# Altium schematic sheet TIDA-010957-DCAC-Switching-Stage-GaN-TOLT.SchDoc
size 558 x 431 mm; Date: Not shown in title block; ApprovedBy: Not shown in title block; CheckedBy: Not shown in title block; Author: Not shown in title block; CompanyName: Not shown in title block; Engineer: Not shown in title block; Organization: Not shown in title block; Address1: Not shown in title block; Address2: Not shown in title block; Address3: Not shown in title block; Address4: Not shown in title block; DocumentNumber: 1; Revision: Use project parameter SCH_Rev; SheetNumber: 12; SheetTotal: 12; PageSetup: Record=PageOptions¦CenterHorizontal=True¦CenterVertical=True¦PrintScale=1.00¦XCorrection=1.00¦YCorrection=1.00¦PrintKind=0¦BorderSize=5000000¦LeftOffset=0¦BottomOffset=0¦Orientation=2¦PaperLength=1000¦PaperWidth=1000¦Scale=100¦PaperSource=15¦PrintQuality=600¦MediaType=1¦DitherType=10¦PaperKind=Letter¦PrintScaleMode=1
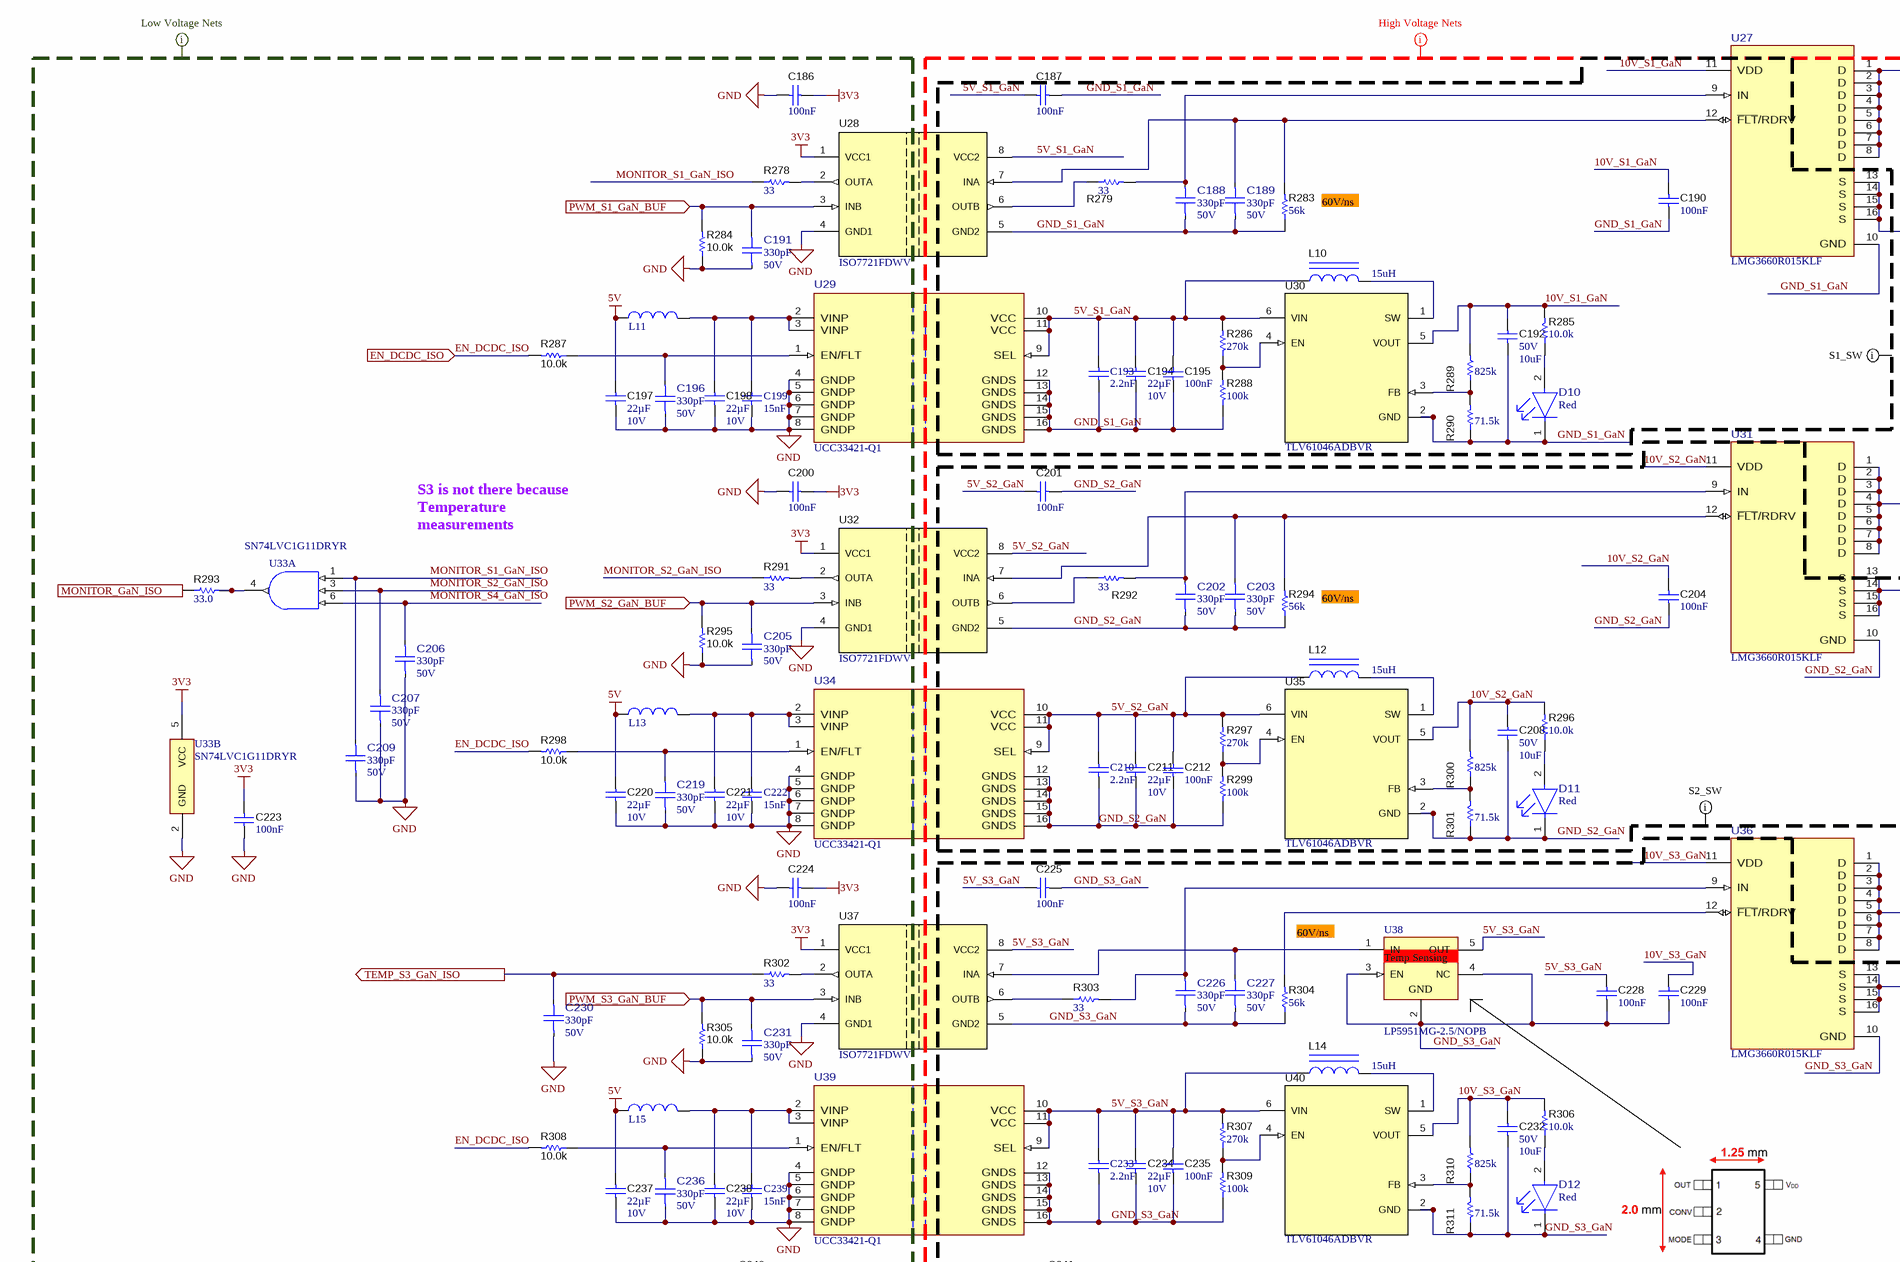
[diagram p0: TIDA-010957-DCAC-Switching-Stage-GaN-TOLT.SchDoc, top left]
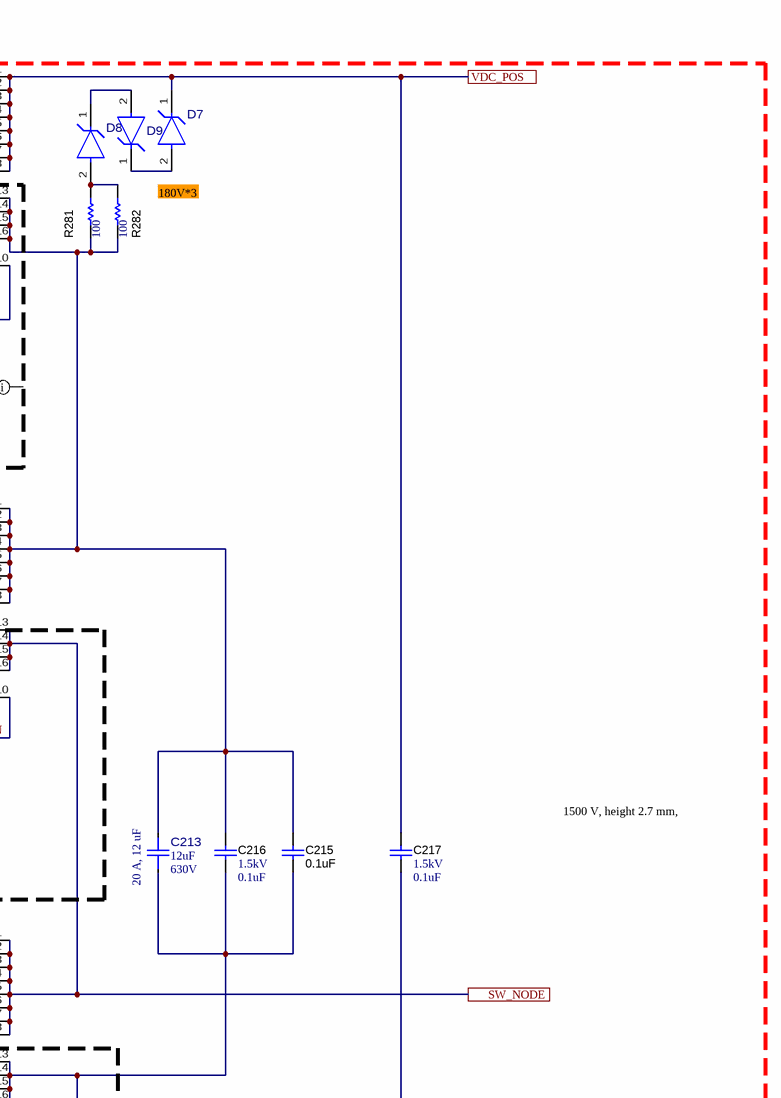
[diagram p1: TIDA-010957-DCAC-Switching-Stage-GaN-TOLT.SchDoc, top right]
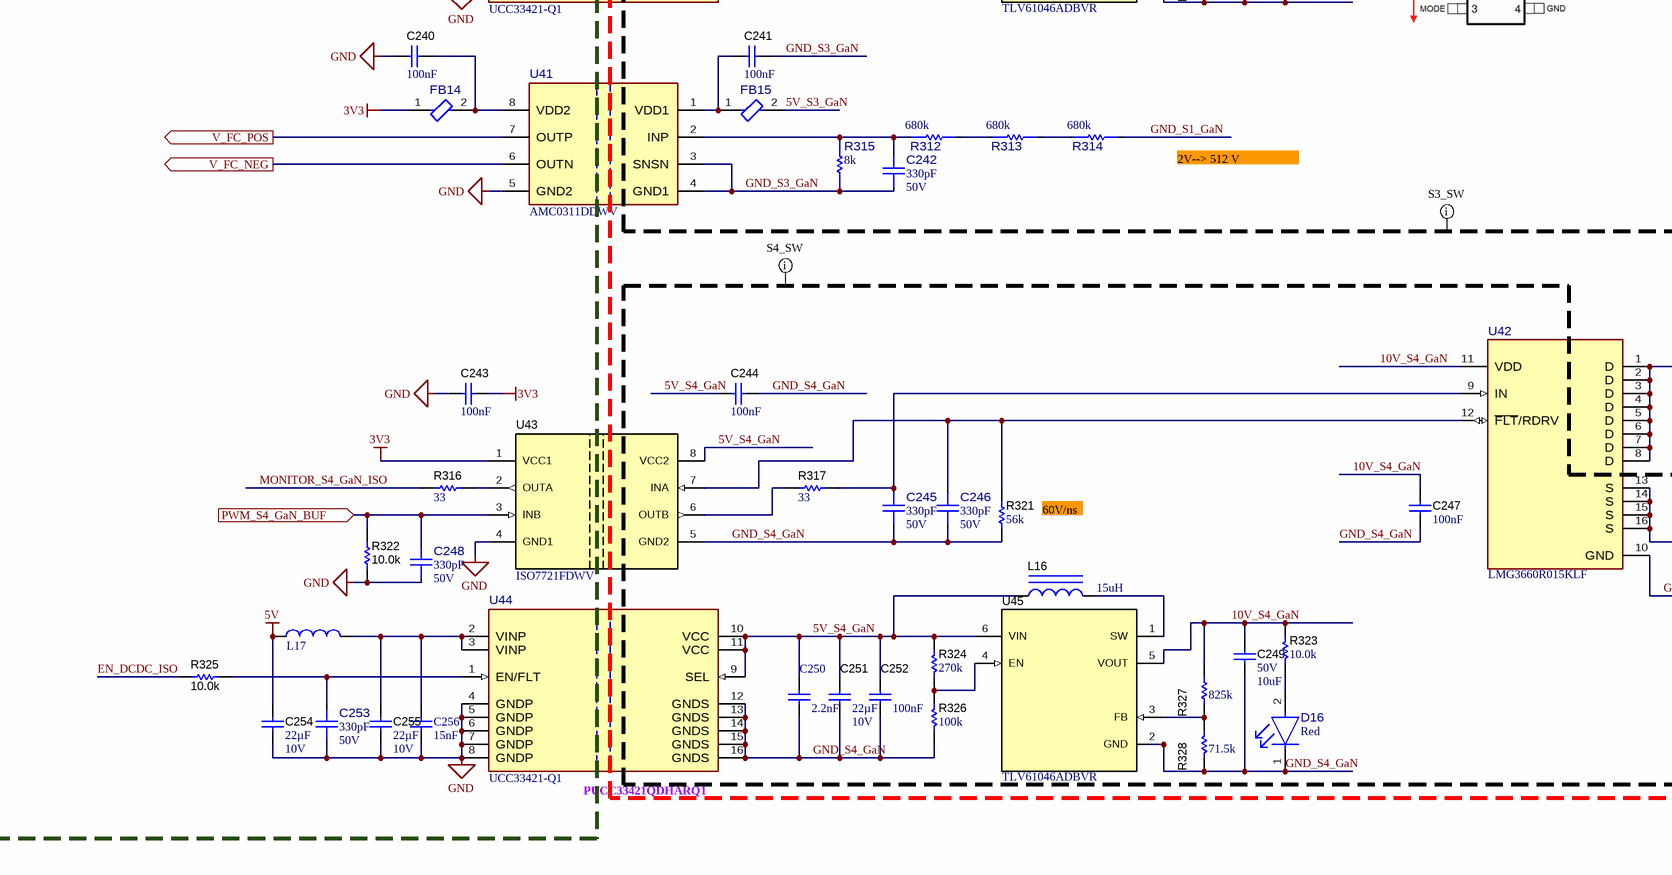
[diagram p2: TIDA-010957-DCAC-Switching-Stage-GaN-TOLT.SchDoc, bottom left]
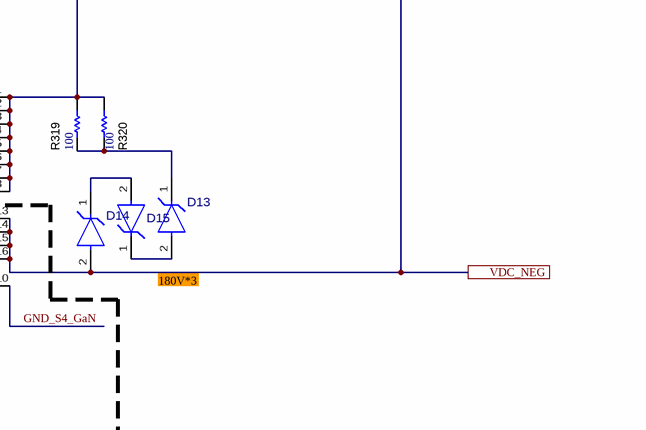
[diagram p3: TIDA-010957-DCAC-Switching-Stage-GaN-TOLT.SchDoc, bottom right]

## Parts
C186  Cap_F: 100nF  [0603]  (hidden comment: 06033C104JAT2A)
C187  Cap_F: 100nF  [0603]  (hidden comment: 06033C104JAT2A)
C188  ValueDisplayed: 330pF  VDC_V: 50V  [FP-CGA3E2C0G1H331J080AA_0603-MFG]  (hidden comment: CGA3E2C0G1H331J080AA)
C189  ValueDisplayed: 330pF  VDC_V: 50V  [FP-CGA3E2C0G1H331J080AA_0603-MFG]  (hidden comment: CGA3E2C0G1H331J080AA)
C190  Cap_F: 100nF  [0603]  (hidden comment: 06033C104JAT2A)
C191  ValueDisplayed: 330pF  VDC_V: 50V  [FP-CGA3E2C0G1H331J080AA_0603-MFG]  (hidden comment: CGA3E2C0G1H331J080AA)
C192  VDC_V: 50V  ValueDisplayed: 10uF  [1206_180]  (hidden comment: GRT31CR61H106KE01L)
C193  Cap_F: 2.2nF  [WCAP-CSGP_0402_L1W0.5H0.5]  (hidden comment: 885012205063)
C194  Cap_F: 22µF  VDC_V: 10V  [0805_HV]  (hidden comment: GRM21BZ71A226ME15L)
C195  Cap_F: 100nF  [0603]  (hidden comment: 06033C104JAT2A)
C196  ValueDisplayed: 330pF  VDC_V: 50V  [FP-CGA3E2C0G1H331J080AA_0603-MFG]  (hidden comment: CGA3E2C0G1H331J080AA)
C197  Cap_F: 22µF  VDC_V: 10V  [0805_HV]  (hidden comment: GRM21BZ71A226ME15L)
C198  Cap_F: 22µF  VDC_V: 10V  [0805_HV]  (hidden comment: GRM21BZ71A226ME15L)
C199  Cap_F: 15nF  [WCAP-CSGP_0402_L1W0.5H0.5]  (hidden comment: 885012205051)
C200  Cap_F: 100nF  [0603]  (hidden comment: 06033C104JAT2A)
C201  Cap_F: 100nF  [0603]  (hidden comment: 06033C104JAT2A)
C202  ValueDisplayed: 330pF  VDC_V: 50V  [FP-CGA3E2C0G1H331J080AA_0603-MFG]  (hidden comment: CGA3E2C0G1H331J080AA)
C203  ValueDisplayed: 330pF  VDC_V: 50V  [FP-CGA3E2C0G1H331J080AA_0603-MFG]  (hidden comment: CGA3E2C0G1H331J080AA)
C204  Cap_F: 100nF  [0603]  (hidden comment: 06033C104JAT2A)
C205  ValueDisplayed: 330pF  VDC_V: 50V  [FP-CGA3E2C0G1H331J080AA_0603-MFG]  (hidden comment: CGA3E2C0G1H331J080AA)
C206  ValueDisplayed: 330pF  VDC_V: 50V  [FP-CGA3E2C0G1H331J080AA_0603-MFG]  (hidden comment: CGA3E2C0G1H331J080AA)
C207  ValueDisplayed: 330pF  VDC_V: 50V  [FP-CGA3E2C0G1H331J080AA_0603-MFG]  (hidden comment: CGA3E2C0G1H331J080AA)
C208  VDC_V: 50V  ValueDisplayed: 10uF  [1206_180]  (hidden comment: GRT31CR61H106KE01L)
C209  ValueDisplayed: 330pF  VDC_V: 50V  [FP-CGA3E2C0G1H331J080AA_0603-MFG]  (hidden comment: CGA3E2C0G1H331J080AA)
C210  Cap_F: 2.2nF  [WCAP-CSGP_0402_L1W0.5H0.5]  (hidden comment: 885012205063)
C211  Cap_F: 22µF  VDC_V: 10V  [0805_HV]  (hidden comment: GRM21BZ71A226ME15L)
C212  Cap_F: 100nF  [0603]  (hidden comment: 06033C104JAT2A)
C213  ValueDisplayed: 12uF  VDC_V: 630V  [FP-B32676G6126K000_RADIAL-MFG]  (hidden comment: B32676G6126K000)
C215  ValueDisplayed: 0.1uF  [1812_254]  (hidden comment: C1812W104KDRACTU)
C216  VDC_V: 1.5kV  ValueDisplayed: 0.1uF  [2225]  (hidden comment: C2225C104KFRACTU)
C217  VDC_V: 1.5kV  ValueDisplayed: 0.1uF  [2225]  (hidden comment: C2225C104KFRACTU)
C219  ValueDisplayed: 330pF  VDC_V: 50V  [FP-CGA3E2C0G1H331J080AA_0603-MFG]  (hidden comment: CGA3E2C0G1H331J080AA)
C220  Cap_F: 22µF  VDC_V: 10V  [0805_HV]  (hidden comment: GRM21BZ71A226ME15L)
C221  Cap_F: 22µF  VDC_V: 10V  [0805_HV]  (hidden comment: GRM21BZ71A226ME15L)
C222  Cap_F: 15nF  [WCAP-CSGP_0402_L1W0.5H0.5]  (hidden comment: 885012205051)
C223  Cap_F: 100nF  [0603]  (hidden comment: 06033C104JAT2A)
C224  Cap_F: 100nF  [0603]  (hidden comment: 06033C104JAT2A)
C225  Cap_F: 100nF  [0603]  (hidden comment: 06033C104JAT2A)
C226  ValueDisplayed: 330pF  VDC_V: 50V  [FP-CGA3E2C0G1H331J080AA_0603-MFG]  (hidden comment: CGA3E2C0G1H331J080AA)
C227  ValueDisplayed: 330pF  VDC_V: 50V  [FP-CGA3E2C0G1H331J080AA_0603-MFG]  (hidden comment: CGA3E2C0G1H331J080AA)
C228  Cap_F: 100nF  [0603]  (hidden comment: 06033C104JAT2A)
C229  Cap_F: 100nF  [0603]  (hidden comment: 06033C104JAT2A)
C230  ValueDisplayed: 330pF  VDC_V: 50V  [FP-CGA3E2C0G1H331J080AA_0603-MFG]  (hidden comment: CGA3E2C0G1H331J080AA)
C231  ValueDisplayed: 330pF  VDC_V: 50V  [FP-CGA3E2C0G1H331J080AA_0603-MFG]  (hidden comment: CGA3E2C0G1H331J080AA)
C232  VDC_V: 50V  ValueDisplayed: 10uF  [1206_180]  (hidden comment: GRT31CR61H106KE01L)
C233  Cap_F: 2.2nF  [WCAP-CSGP_0402_L1W0.5H0.5]  (hidden comment: 885012205063)
C234  Cap_F: 22µF  VDC_V: 10V  [0805_HV]  (hidden comment: GRM21BZ71A226ME15L)
C235  Cap_F: 100nF  [0603]  (hidden comment: 06033C104JAT2A)
C236  ValueDisplayed: 330pF  VDC_V: 50V  [FP-CGA3E2C0G1H331J080AA_0603-MFG]  (hidden comment: CGA3E2C0G1H331J080AA)
C237  Cap_F: 22µF  VDC_V: 10V  [0805_HV]  (hidden comment: GRM21BZ71A226ME15L)
C238  Cap_F: 22µF  VDC_V: 10V  [0805_HV]  (hidden comment: GRM21BZ71A226ME15L)
C239  Cap_F: 15nF  [WCAP-CSGP_0402_L1W0.5H0.5]  (hidden comment: 885012205051)
C240  Cap_F: 100nF  [0603]  (hidden comment: 06033C104JAT2A)
C241  Cap_F: 100nF  [0603]  (hidden comment: 06033C104JAT2A)
C242  ValueDisplayed: 330pF  VDC_V: 50V  [FP-CGA3E2C0G1H331J080AA_0603-MFG]  (hidden comment: CGA3E2C0G1H331J080AA)
C243  Cap_F: 100nF  [0603]  (hidden comment: 06033C104JAT2A)
C244  Cap_F: 100nF  [0603]  (hidden comment: 06033C104JAT2A)
C245  ValueDisplayed: 330pF  VDC_V: 50V  [FP-CGA3E2C0G1H331J080AA_0603-MFG]  (hidden comment: CGA3E2C0G1H331J080AA)
C246  ValueDisplayed: 330pF  VDC_V: 50V  [FP-CGA3E2C0G1H331J080AA_0603-MFG]  (hidden comment: CGA3E2C0G1H331J080AA)
C247  Cap_F: 100nF  [0603]  (hidden comment: 06033C104JAT2A)
C248  ValueDisplayed: 330pF  VDC_V: 50V  [FP-CGA3E2C0G1H331J080AA_0603-MFG]  (hidden comment: CGA3E2C0G1H331J080AA)
C249  VDC_V: 50V  ValueDisplayed: 10uF  [1206_180]  (hidden comment: GRT31CR61H106KE01L)
C250  Cap_F: 2.2nF  [WCAP-CSGP_0402_L1W0.5H0.5]  (hidden comment: 885012205063)
C251  Cap_F: 22µF  VDC_V: 10V  [0805_HV]  (hidden comment: GRM21BZ71A226ME15L)
C252  Cap_F: 100nF  [0603]  (hidden comment: 06033C104JAT2A)
C253  ValueDisplayed: 330pF  VDC_V: 50V  [FP-CGA3E2C0G1H331J080AA_0603-MFG]  (hidden comment: CGA3E2C0G1H331J080AA)
C254  Cap_F: 22µF  VDC_V: 10V  [0805_HV]  (hidden comment: GRM21BZ71A226ME15L)
C255  Cap_F: 22µF  VDC_V: 10V  [0805_HV]  (hidden comment: GRM21BZ71A226ME15L)
C256  Cap_F: 15nF  [WCAP-CSGP_0402_L1W0.5H0.5]  (hidden comment: 885012205051)
D7  ZGL41-180A-E3/96  [FP-ZGL41-180A-E3/96_GL41-MFG]  (value not drawn)
D8  ZGL41-180A-E3/96  [FP-ZGL41-180A-E3/96_GL41-MFG]  (value not drawn)
D9  ZGL41-180A-E3/96  [FP-ZGL41-180A-E3/96_GL41-MFG]  (value not drawn)
D10  Color: Red  [FP-APG1608SURKC_T_0603-MFG]  (hidden comment: APG1608SURKC/T)
D11  Color: Red  [FP-APG1608SURKC_T_0603-MFG]  (hidden comment: APG1608SURKC/T)
D12  Color: Red  [FP-APG1608SURKC_T_0603-MFG]  (hidden comment: APG1608SURKC/T)
D13  ZGL41-180A-E3/96  [FP-ZGL41-180A-E3/96_GL41-MFG]  (value not drawn)
D14  ZGL41-180A-E3/96  [FP-ZGL41-180A-E3/96_GL41-MFG]  (value not drawn)
D15  ZGL41-180A-E3/96  [FP-ZGL41-180A-E3/96_GL41-MFG]  (value not drawn)
D16  Color: Red  [FP-APG1608SURKC_T_0603-MFG]  (hidden comment: APG1608SURKC/T)
FB14  MH1608-601Y  [FP-MH1608-601Y_0603-MFG]  (value not drawn)
FB15  MH1608-601Y  [FP-MH1608-601Y_0603-MFG]  (value not drawn)
L10  ValueDisplayed: 15uH  [SDR0302]  (hidden comment: SDR0302-150ML)
L11  74479763222  [WE-PMI_0603_L1.6W0.8H0.8]  (value not drawn)
L12  ValueDisplayed: 15uH  [SDR0302]  (hidden comment: SDR0302-150ML)
L13  74479763222  [WE-PMI_0603_L1.6W0.8H0.8]  (value not drawn)
L14  ValueDisplayed: 15uH  [SDR0302]  (hidden comment: SDR0302-150ML)
L15  74479763222  [WE-PMI_0603_L1.6W0.8H0.8]  (value not drawn)
L16  ValueDisplayed: 15uH  [SDR0302]  (hidden comment: SDR0302-150ML)
L17  74479763222  [WE-PMI_0603_L1.6W0.8H0.8]  (value not drawn)
R278  ValueDisplayed: 33  [0603]  (hidden comment: CRCW060333R0JNEA)
R279  ValueDisplayed: 33  [0603]  (hidden comment: CRCW060333R0JNEA)
R281  ValueDisplayed: 100  [1206]  (hidden comment: CRCW1206100RFKEAHP)
R282  ValueDisplayed: 100  [1206]  (hidden comment: CRCW1206100RFKEAHP)
R283  ValueDisplayed: 56k  [0603]  (hidden comment: CRCW060356K0JNEA)
R284  ValueDisplayed: 10.0k  [0603]  (hidden comment: CRCW060310K0FKEA)
R285  ValueDisplayed: 10.0k  [0603]  (hidden comment: RC0603FR-0710KL)
R286  ValueDisplayed: 270k  [0603]  (hidden comment: RC0603FR-07270KL)
R287  ValueDisplayed: 10.0k  [0603]  (hidden comment: CRCW060310K0FKEA)
R288  ValueDisplayed: 100k  [0603]  (hidden comment: RC0603FR-07100KL)
R289  ValueDisplayed: 825k  [0603]  (hidden comment: RC0603FR-07825KL)
R290  ValueDisplayed: 71.5k  [0603]  (hidden comment: RC0603FR-0771K5L)
R291  ValueDisplayed: 33  [0603]  (hidden comment: CRCW060333R0JNEA)
R292  ValueDisplayed: 33  [0603]  (hidden comment: CRCW060333R0JNEA)
R293  ValueDisplayed: 33.0  [0402L]  (hidden comment: ERJ-2RKF33R0X)
R294  ValueDisplayed: 56k  [0603]  (hidden comment: CRCW060356K0JNEA)
R295  ValueDisplayed: 10.0k  [0603]  (hidden comment: CRCW060310K0FKEA)
R296  ValueDisplayed: 10.0k  [0603]  (hidden comment: RC0603FR-0710KL)
R297  ValueDisplayed: 270k  [0603]  (hidden comment: RC0603FR-07270KL)
R298  ValueDisplayed: 10.0k  [0603]  (hidden comment: CRCW060310K0FKEA)
R299  ValueDisplayed: 100k  [0603]  (hidden comment: RC0603FR-07100KL)
R300  ValueDisplayed: 825k  [0603]  (hidden comment: RC0603FR-07825KL)
R301  ValueDisplayed: 71.5k  [0603]  (hidden comment: RC0603FR-0771K5L)
R302  ValueDisplayed: 33  [0603]  (hidden comment: CRCW060333R0JNEA)
R303  ValueDisplayed: 33  [0603]  (hidden comment: CRCW060333R0JNEA)
R304  ValueDisplayed: 56k  [0603]  (hidden comment: CRCW060356K0JNEA)
R305  ValueDisplayed: 10.0k  [0603]  (hidden comment: CRCW060310K0FKEA)
R306  ValueDisplayed: 10.0k  [0603]  (hidden comment: RC0603FR-0710KL)
R307  ValueDisplayed: 270k  [0603]  (hidden comment: RC0603FR-07270KL)
R308  ValueDisplayed: 10.0k  [0603]  (hidden comment: CRCW060310K0FKEA)
R309  ValueDisplayed: 100k  [0603]  (hidden comment: RC0603FR-07100KL)
R310  ValueDisplayed: 825k  [0603]  (hidden comment: RC0603FR-07825KL)
R311  ValueDisplayed: 71.5k  [0603]  (hidden comment: RC0603FR-0771K5L)
R312  value 680k  [FP-TNPV0805680KBEEA_0805-MFG]  (hidden comment: TNPV0805680KBEEA)
R313  value 680k  [FP-TNPV0805680KBEEA_0805-MFG]  (hidden comment: TNPV0805680KBEEA)
R314  value 680k  [FP-TNPV0805680KBEEA_0805-MFG]  (hidden comment: TNPV0805680KBEEA)
R315  value 8k  [FP-RT0603BRE078KL_0603-MFG]  (hidden comment: RT0603BRE078KL)
R316  ValueDisplayed: 33  [0603]  (hidden comment: CRCW060333R0JNEA)
R317  ValueDisplayed: 33  [0603]  (hidden comment: CRCW060333R0JNEA)
R319  ValueDisplayed: 100  [1206]  (hidden comment: CRCW1206100RFKEAHP)
R320  ValueDisplayed: 100  [1206]  (hidden comment: CRCW1206100RFKEAHP)
R321  ValueDisplayed: 56k  [0603]  (hidden comment: CRCW060356K0JNEA)
R322  ValueDisplayed: 10.0k  [0603]  (hidden comment: CRCW060310K0FKEA)
R323  ValueDisplayed: 10.0k  [0603]  (hidden comment: RC0603FR-0710KL)
R324  ValueDisplayed: 270k  [0603]  (hidden comment: RC0603FR-07270KL)
R325  ValueDisplayed: 10.0k  [0603]  (hidden comment: CRCW060310K0FKEA)
R326  ValueDisplayed: 100k  [0603]  (hidden comment: RC0603FR-07100KL)
R327  ValueDisplayed: 825k  [0603]  (hidden comment: RC0603FR-07825KL)
R328  ValueDisplayed: 71.5k  [0603]  (hidden comment: RC0603FR-0771K5L)
U27  LMG3660R015KLF  [KLF0016A-MFG]
U28  ISO7721FDWV  [DWV0008A]
U29  UCC33421-Q1  [DWX0016A-MFG]
U30  TLV61046ADBVR  [DBV0006A_N]
U31  LMG3660R015KLF  [KLF0016A-MFG]
U32  ISO7721FDWV  [DWV0008A]
U33  SN74LVC1G11DRYR  [DRY0006A]  (parts A,B of 2)
U34  UCC33421-Q1  [DWX0016A-MFG]
U35  TLV61046ADBVR  [DBV0006A_N]
U36  LMG3660R015KLF  [KLF0016A-MFG]
U37  ISO7721FDWV  [DWV0008A]
U38  LP5951MG-2.5/NOPB  [DCK0005A_N]
U39  UCC33421-Q1  [DWX0016A-MFG]
U40  TLV61046ADBVR  [DBV0006A_N]
U41  AMC0311DDWV  [DWV0008A-MFG]
U42  LMG3660R015KLF  [KLF0016A-MFG]
U43  ISO7721FDWV  [DWV0008A]
U44  UCC33421-Q1  [DWX0016A-MFG]
U45  TLV61046ADBVR  [DBV0006A_N]

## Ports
EN_DCDC_ISO (in), MONITOR_GaN_ISO (out), PWM_S1_GaN_BUF (in), PWM_S2_GaN_BUF (in), PWM_S3_GaN_BUF (in), PWM_S4_GaN_BUF (in), SW_NODE, TEMP_S3_GaN_ISO (out), V_FC_NEG (out), V_FC_POS (out), VDC_NEG, VDC_POS

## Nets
3V3: C186.1 C200.1 C223.1 C224.1 C243.1 FB14.1 U28.1(VCC1) U32.1(VCC1) U33.5(VCC) U37.1(VCC1) U43.1(VCC1)
5V: C197.1 C220.1 C237.1 C254.1 L11.2 L13.2 L15.2 L17.2
GND: C186.2 C191.1 C196.1 C197.2 C198.2 C199.1 C200.2 C205.1 C206.1 C207.1 C209.1 C219.1 C220.2 C221.2 C222.1 C223.2 C224.2 C230.1 C231.1 C236.1 C237.2 C238.2 C239.1 C240.2 C243.2 C248.1 C253.1 C254.2 C255.2 C256.1 R284.1 R295.1 R305.1 R322.1 U28.4(GND1) U29.4(GNDP) U29.5(GNDP) U29.6(GNDP) U29.7(GNDP) U29.8(GNDP) U32.4(GND1) U33.2(GND) U34.4(GNDP) U34.5(GNDP) U34.6(GNDP) U34.7(GNDP) U34.8(GNDP) U37.4(GND1) U39.4(GNDP) U39.5(GNDP) U39.6(GNDP) U39.7(GNDP) U39.8(GNDP) U41.5(GND2) U43.4(GND1) U44.4(GNDP) U44.5(GNDP) U44.6(GNDP) U44.7(GNDP) U44.8(GNDP)
5V_S1_GaN: C187.1 C193.2 C194.1 C195.1 L10.2 R286.2 U28.8(VCC2) U29.9(SEL) U29.10(VCC) U29.11(VCC) U30.6(VIN)
5V_S2_GaN: C201.1 C210.2 C211.1 C212.1 L12.2 R297.2 U32.8(VCC2) U34.9(SEL) U34.10(VCC) U34.11(VCC) U35.6(VIN)
5V_S3_GaN: C225.1 C228.1 C233.2 C234.1 C235.1 FB15.2 L14.2 R307.2 U37.8(VCC2) U38.5(OUT) U39.9(SEL) U39.10(VCC) U39.11(VCC) U40.6(VIN)
5V_S4_GaN: C244.1 C250.2 C251.1 C252.1 L16.2 R324.2 U43.8(VCC2) U44.9(SEL) U44.10(VCC) U44.11(VCC) U45.6(VIN)
10V_S1_GaN: C190.1 C192.1 R285.2 R289.2 U27.11(VDD) U30.5(VOUT)
10V_S2_GaN: C204.1 C208.1 R296.2 R300.2 U31.11(VDD) U35.5(VOUT)
10V_S3_GaN: C229.1 C232.1 R306.2 R310.2 U36.11(VDD) U40.5(VOUT)
10V_S4_GaN: C247.1 C249.1 R323.2 R327.2 U42.11(VDD) U45.5(VOUT)
EN_DCDC_ISO: R287.2 R298.2 R308.2 R325.2 ; port EN_DCDC_ISO
GND_S1_GaN: C187.2 C188.1 C189.1 C190.2 C192.2 C193.1 C194.2 C195.2 D10.1(CATHODE) R283.1 R288.1 R290.1 R314.2 U27.10(GND) U28.5(GND2) U29.12(GNDS) U29.13(GNDS) U29.14(GNDS) U29.15(GNDS) U29.16(GNDS) U30.2(GND)
GND_S2_GaN: C201.2 C202.1 C203.1 C204.2 C208.2 C210.1 C211.2 C212.2 D11.1(CATHODE) R294.1 R299.1 R301.1 U31.10(GND) U32.5(GND2) U34.12(GNDS) U34.13(GNDS) U34.14(GNDS) U34.15(GNDS) U34.16(GNDS) U35.2(GND)
GND_S3_GaN: C225.2 C226.1 C227.1 C228.2 C229.2 C232.2 C233.1 C234.2 C235.2 C241.2 C242.1 D12.1(CATHODE) R304.1 R309.1 R311.1 R315.1 U36.10(GND) U37.5(GND2) U38.2(GND) U38.3(EN) U38.4(NC) U39.12(GNDS) U39.13(GNDS) U39.14(GNDS) U39.15(GNDS) U39.16(GNDS) U40.2(GND) U41.3(SNSN) U41.4(GND1)
GND_S4_GaN: C244.2 C245.1 C246.1 C247.2 C249.2 C250.1 C251.2 C252.2 D16.1(CATHODE) R321.1 R326.1 R328.1 U42.10(GND) U43.5(GND2) U44.12(GNDS) U44.13(GNDS) U44.14(GNDS) U44.15(GNDS) U44.16(GNDS) U45.2(GND)
MONITOR_GaN_ISO: R293.1 ; port MONITOR_GaN_ISO
MONITOR_S1_GaN_ISO: C209.2 R278.1 U33.1(A)
MONITOR_S2_GaN_ISO: C207.2 R291.1 U33.3(B)
MONITOR_S4_GaN_ISO: C206.2 R316.1 U33.6(C)
PWM_S1_GaN_BUF: C191.2 R284.2 U28.3(INB) ; port PWM_S1_GaN_BUF
PWM_S2_GaN_BUF: C205.2 R295.2 U32.3(INB) ; port PWM_S2_GaN_BUF
PWM_S3_GaN_BUF: C231.2 R305.2 U37.3(INB) ; port PWM_S3_GaN_BUF
PWM_S4_GaN_BUF: C248.2 R322.2 U43.3(INB) ; port PWM_S4_GaN_BUF
SW_NODE: U31.13(S) U31.14(S) U31.15(S) U31.16(S) U36.1(D) U36.2(D) U36.3(D) U36.4(D) U36.5(D) U36.6(D) U36.7(D) U36.8(D) ; port SW_NODE
TEMP_S3_GaN_ISO: C230.2 R302.1 ; port TEMP_S3_GaN_ISO
V_FC_NEG: U41.6(OUTN) ; port V_FC_NEG
V_FC_POS: U41.7(OUTP) ; port V_FC_POS
VDC_NEG: C217.2 D14.2(ANODE) U42.13(S) U42.14(S) U42.15(S) U42.16(S) ; port VDC_NEG
VDC_POS: C217.1 D7.1(CATHODE) U27.1(D) U27.2(D) U27.3(D) U27.4(D) U27.5(D) U27.6(D) U27.7(D) U27.8(D) ; port VDC_POS
NetC188_2: C188.2 R279.2 U27.9(IN)
NetC189_2: C189.2 R283.2 U27.12(~{FLT}/RDRV) U28.7(INA)
NetC196_2: C196.2 R287.1 U29.1(EN/FLT)
NetC198_1: C198.1 C199.2 L11.1 U29.2(VINP) U29.3(VINP)
NetC202_2: C202.2 R292.2 U31.9(IN)
NetC203_2: C203.2 R294.2 U31.12(~{FLT}/RDRV) U32.7(INA)
NetC213_1: C213.1 C215.1 C216.2 R319.2 R320.2 U36.13(S) U36.14(S) U36.15(S) U36.16(S) U42.1(D) U42.2(D) U42.3(D) U42.4(D) U42.5(D) U42.6(D) U42.7(D) U42.8(D)
NetC213_2: C213.2 C215.2 C216.1 R281.1 R282.1 U27.13(S) U27.14(S) U27.15(S) U27.16(S) U31.1(D) U31.2(D) U31.3(D) U31.4(D) U31.5(D) U31.6(D) U31.7(D) U31.8(D)
NetC219_2: C219.2 R298.1 U34.1(EN/FLT)
NetC221_1: C221.1 C222.2 L13.1 U34.2(VINP) U34.3(VINP)
NetC226_2: C226.2 R303.2 U36.9(IN)
NetC227_2: C227.2 U37.7(INA) U38.1(IN)
NetC236_2: C236.2 R308.1 U39.1(EN/FLT)
NetC238_1: C238.1 C239.2 L15.1 U39.2(VINP) U39.3(VINP)
NetC240_1: C240.1 FB14.2 U41.8(VDD2)
NetC241_1: C241.1 FB15.1 U41.1(VDD1)
NetC242_2: C242.2 R312.1 R315.2 U41.2(INP)
NetC245_2: C245.2 R317.2 U42.9(IN)
NetC246_2: C246.2 R321.2 U42.12(~{FLT}/RDRV) U43.7(INA)
NetC253_2: C253.2 R325.1 U44.1(EN/FLT)
NetC255_1: C255.1 C256.2 L17.1 U44.2(VINP) U44.3(VINP)
NetD7_2: D7.2(ANODE) D9.1(CATHODE)
NetD8_1: D8.1(CATHODE) D9.2(ANODE)
NetD8_2: D8.2(ANODE) R281.2 R282.2
NetD10_2: D10.2(ANODE) R285.1
NetD11_2: D11.2(ANODE) R296.1
NetD12_2: D12.2(ANODE) R306.1
NetD13_1: D13.1(CATHODE) R319.1 R320.1
NetD13_2: D13.2(ANODE) D15.1(CATHODE)
NetD14_1: D14.1(CATHODE) D15.2(ANODE)
NetD16_2: D16.2(ANODE) R323.1
NetL10_1: L10.1 U30.1(SW)
NetL12_1: L12.1 U35.1(SW)
NetL14_1: L14.1 U40.1(SW)
NetL16_1: L16.1 U45.1(SW)
NetR278_2: R278.2 U28.2(OUTA)
NetR279_1: R279.1 U28.6(OUTB)
NetR286_1: R286.1 R288.2 U30.4(EN)
NetR289_1: R289.1 R290.2 U30.3(FB)
NetR291_2: R291.2 U32.2(OUTA)
NetR292_1: R292.1 U32.6(OUTB)
NetR293_2: R293.2 U33.4(Y)
NetR297_1: R297.1 R299.2 U35.4(EN)
NetR300_1: R300.1 R301.2 U35.3(FB)
NetR302_2: R302.2 U37.2(OUTA)
NetR303_1: R303.1 U37.6(OUTB)
NetR304_2: R304.2 U36.12(~{FLT}/RDRV)
NetR307_1: R307.1 R309.2 U40.4(EN)
NetR310_1: R310.1 R311.2 U40.3(FB)
NetR312_2: R312.2 R313.1
NetR313_2: R313.2 R314.1
NetR316_2: R316.2 U43.2(OUTA)
NetR317_1: R317.1 U43.6(OUTB)
NetR324_1: R324.1 R326.2 U45.4(EN)
NetR327_1: R327.1 R328.2 U45.3(FB)

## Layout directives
net class LV_NET: 3V3, 5V, EN_DCDC_ISO, GND, MONITOR_S1_GaN_ISO, MONITOR_S2_GaN_ISO, MONITOR_S4_GaN_ISO
net class HV_NET: 5V_S1_GaN, 5V_S2_GaN, 5V_S3_GaN, 5V_S4_GaN, 10V_S1_GaN, 10V_S2_GaN, 10V_S3_GaN, 10V_S4_GaN, GND_S1_GaN, GND_S2_GaN, GND_S3_GaN, GND_S4_GaN
net class S4_SW: 5V_S1_GaN, 5V_S2_GaN, 5V_S3_GaN, 5V_S4_GaN, 10V_S1_GaN, 10V_S2_GaN, 10V_S3_GaN, 10V_S4_GaN, GND_S1_GaN, GND_S2_GaN, GND_S3_GaN, GND_S4_GaN
net class S3_SW: 5V_S1_GaN, 5V_S2_GaN, 5V_S3_GaN, 5V_S4_GaN, 10V_S1_GaN, 10V_S2_GaN, 10V_S3_GaN, 10V_S4_GaN, GND_S1_GaN, GND_S2_GaN, GND_S3_GaN, GND_S4_GaN
net class S2_SW: 5V_S1_GaN, 5V_S2_GaN, 5V_S3_GaN, 5V_S4_GaN, 10V_S1_GaN, 10V_S2_GaN, 10V_S3_GaN, 10V_S4_GaN, GND_S1_GaN, GND_S2_GaN, GND_S3_GaN, GND_S4_GaN
net class S1_SW: 5V_S1_GaN, 5V_S2_GaN, 5V_S3_GaN, 5V_S4_GaN, 10V_S1_GaN, 10V_S2_GaN, 10V_S3_GaN, 10V_S4_GaN, GND_S1_GaN, GND_S2_GaN, GND_S3_GaN, GND_S4_GaN

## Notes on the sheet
- 180V*3
- (near R283) 60V/ns
- S3 is not there because Temperature measurements
- (near R294) 60V/ns
- 1500 V, height 2.7 mm, 100 nF,
- (near C213) 20 A, 12 uF
- 60V/ns
- (near U38) Temp Sensing
- 2V--> 512 V
- (near R321) 60V/ns
- (near U44) PUCC33421QDHARQ1

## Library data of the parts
C186 C187 C190 C195 C200 C201 C204 C212 C223-C225 C228 C229 C235 C240 C241 C243 C244 C247 C252 = CMP-0006752-5: CAP, CERM, 0.1 uF, 25 V, +/- 5%, X7R, 0603; Manufacturer: AVX; TaMin_C: -55°C; ESR_ohm: 0.05; Polarized: N; SizeAreaWB_mm2: 4.68; Value1: 0.05 ohm; U/M: EA; Value: 0.1uF; TaMax_C: 125°C; SizeZ_mm: 1; SizeX_mm: 1.6; SizeY_mm: 0.8; Value2: 25V; SizeArea_mm2: 1.28; AEC Category: Q200
C188 C189 C191 C196 C202 C203 C205-C207 C209 C219 C226 C227 C230 C231 C236 C242 C245 C246 C248 C253 = CMP-0095085-1: Cap Ceramic 330pF 50V C0G 5% Pad SMD 0603 +125°C Automotive T/R; Manufacturer: TDK; AEC Qualified: Yes; TempCo: 30ppm/°C; Tolerance_%: 0.05%; AEC Grade: Grade 1; SizeZ_mm: 1.1mm
C192 C208 C232 C249 = CMP-0009015-2: CAP, CERM, 10 uF, 50 V, +/- 10%, X5R, AEC-Q200 Grade 1, 1206; Manufacturer: MuRata; TaMin_C: -55°C; Polarized: N; SizeAreaWB_mm2: 10.92; Value1: Unknown; U/M: EA; Value: 10uF; TaMax_C: 85°C; SizeZ_mm: 1.8; SizeX_mm: 3.2; SizeY_mm: 1.6; Cap_Case: 1206; SizeArea_mm2: 5.12; AEC Qualified: Y; Cap_F: 10µF; AEC Grade: 1; AEC Category: Q200
C193 C210 C233 C250 = CMP-0119293-1: WCAP-CSGP Multilayer Ceramic Chip Capacitor, General Purpose, size 0402, X7R, 2.2nF, 50VDC; Manufacturer: Wurth Elektronik; Capacitance Tolerance: +/-10%; Case/Size Code: 0402; Dissipation Factor: 2.5%; Insulation Resistance: 10GOhm; Rated Voltage (DC): 50V; Technical Reference: X7R0402222K050DFCT10000
C194 C197 C198 C211 C220 C221 C234 C237 C238 C251 C254 C255 = CMP-0008377-2: CAP, CERM, 22 uF, 10 V, +/- 20%, X7R, 0805; Manufacturer: MuRata; SizeY_mm: 1.25; Cap_Case: 0805; SizeArea_mm2: 2.5; AEC Qualified: N; AEC Category: Q200; ValueDisplayed: 22uF; TaMin_C: -55°C; SizeAreaWB_mm2: 6.75; Value1: Unknown; U/M: EA; Value: 22uF; TaMax_C: 125°C; SizeZ_mm: 1.45; SizeX_mm: 2
C199 C222 C239 C256 = CMP-0115362-1: WCAP-CSGP Multilayer Ceramic Chip Capacitor, General Purpose, size 0402, X7R, 15nF, 25VDC; Manufacturer: Wurth Elektronik; Capacitance Tolerance: +/-10%; Case/Size Code: 0402; Dissipation Factor: 3.5%; Insulation Resistance: 10GOhm; Rated Voltage (DC): 25V; Technical Reference: X7R0402153K025DFCT10000
C213 = CMP-0124359-1: Cap Film 12uF 630V PP 10% (42 X 28 X 42.5mm) Radial 0.0055 Ohm 100°C Bulk; Manufacturer: TDK; AEC Grade: Grade 2; AEC Qualified: Yes; Cap_F: 12µF; Value: 12µF
C215 = CMP-0009326-2: CAP, CERM, 0.1 uF, 1000 V, +/- 10%, X7R, 1812; Manufacturer: Kemet; Polarized: N; Value: 0.1uF; U/M: EA; Cap_F: 100nF; Value1: Unknown; VDC_V: 1kV; Value2: 1000V; TaMin_C: -55°C; TaMax_C: 125°C; Cap_Case: 1812; AEC Category: Q200; SizeArea_mm2: 14.4; SizeAreaWB_mm2: 23.1; SizeX_mm: 4.5; SizeY_mm: 3.2; SizeZ_mm: 2.54
C216 C217 = CMP-0009331-2: CAP, CERM, 0.1 uF, 1500 V, +/- 10%, X7R, 2225; Manufacturer: Kemet; TaMin_C: -55°C; Polarized: N; SizeAreaWB_mm2: 63.91; Value1: Unknown; U/M: EA; Value: 0.1uF; TaMax_C: 125°C; SizeZ_mm: 2; SizeX_mm: 5.7; SizeY_mm: 6.3; Value2: 1500V; SizeArea_mm2: 35.91; Cap_F: 100nF; AEC Category: Q200
D7-D9 D13-D15 = CMP-0122312-1: Zener Diode 180 V 1 W ±5% Surface Mount DO-213AB (GL41); Manufacturer: Vishay; AEC Qualified: No; SizeZ_mm: 2.67mm; TJmax_C: 150°C; Vf_V: 189V; Vr_V: 136.9V; Max Reverse Leakage Current: 1uA; Power_W: 1000mW; Vz_V: 180V; Zener Impedance: 900Ω
D10-D12 D16 = CMP-0091305-2: Red 630nm LED Indication - Discrete 2V 0603 (1608 Metric); Manufacturer: Kingbright; AEC Qualified: No; Import Ts: 1521847491; Forward Current: 20mA; Vr_V: 5V; Ciiva Ids: 1546259; Luminous Intensity: 110mcd; Power_TotalModule: 75mW; Tjmax_C: 115°C; Led Orientation: Top View; SizeZ_mm: 0.28mm; LambdaP: 645nm; Angle: 120°
FB14 FB15 = CMP-0037505-1: 600 Ohms @ 100 MHz 1 Power, Signal Line Ferrite Bead 0603 (1608 Metric) 1A 200mOhm; Manufacturer: Bourns; DCR_ohm: 0.2; SizeZ_mm: 1mm; AEC Qualified: No; Impedance At Frequency: 600Ω @ 100MHz; Test Frequency: 100MHz; Tolerance_%: 25%
L10 L12 L14 L16 = CMP-0057419-2: Inductor, Drum Core, Ferrite, 15 uH, 0.65 A, 0.4 ohm, SMD; Manufacturer: Bourns; Isat: 0.86A @ 10% inductance drop; Irms: 0.65A @ 40C rise; Green_Lifecycle: Active; SizeAreaWB_mm2: 15.2; DCR_ohm: 4d; Green_REACh: Passed; Value1: 0.4 ohm; Value: 15uH; Imax_A: 6.5dA; SizeZ_mm: 2.5; SizeX_mm: 3; SizeY_mm: 2.8; Value2: 0.65A; SizeArea_mm2: 8.4; Ind_H: 15µH; AEC Category: Q200
L11 L13 L15 L17 = CMP-0100992-1: WE-PMI SMT Power Multilayer Inductor, size 0603, 2.2uH, 0.8A, 375mOhm; Manufacturer: Wurth Elektronik; Case/Size Code: 0603; Inductance Tolerance: 20%; Q Factor: 15; Saturation Current: 0.28A; Self Resonant Frequency: 80MHz; Type: Low RDC
R278 R279 R291 R292 R302 R303 R316 R317 = CMP-0025787-4: RES, 33, 5%, 0.1 W, AEC-Q200 Grade 0, 0603; Manufacturer: Vishay-Dale; Power_W: 100mW; TempCo: 200 ppm/C; Value_Code: 33R0; Value: 33; EIA_Code: E24; SizeX_mm: 1.6; SizeY_mm: 0.8; SizeZ_mm: 1; Value2: 0.1W; SizeArea_mm2: 1.28; AEC Qualified: Y; VDC_V: 75V; AEC Category: Q200; AEC Grade: 0
R281 R282 R319 R320 = CMP-0016570-3: RES, 100, 1%, 0.5 W, AEC-Q200 Grade 0, 1206; Manufacturer: Vishay-Dale; Power_W: 500mW; TempCo: 100 ppm/C; Value_Code: 100R; Value: 100; EIA_Code: E96; SizeX_mm: 3.2; SizeY_mm: 1.6; SizeZ_mm: 1.35; Value2: 0.5W; SizeArea_mm2: 5.12; AEC Qualified: Y; AEC Grade: 0; AEC Category: Q200
R283 R294 R304 R321 = CMP-0025828-4: RES, 56 k, 5%, 0.1 W, AEC-Q200 Grade 0, 0603; Manufacturer: Vishay-Dale; Power_W: 100mW; TempCo: 200 ppm/C; Value_Code: 56k0; Value: 56k; EIA_Code: E24; SizeX_mm: 1.6; SizeY_mm: 0.8; SizeZ_mm: 1; Value2: 0.1W; SizeArea_mm2: 1.28; AEC Qualified: Y; VDC_V: 75V; AEC Category: Q200; AEC Grade: 0
R284 R287 R295 R298 R305 R308 R322 R325 = CMP-0021998-4: RES, 10.0 k, 1%, 0.1 W, AEC-Q200 Grade 0, 0603; Manufacturer: Vishay-Dale; Power_W: 100mW; TempCo: 100 ppm/C; Value_Code: 10k0; Value: 10.0k; EIA_Code: E96; Res_ohm: 10k; SizeX_mm: 1.6; SizeY_mm: 0.8; SizeZ_mm: 1; Value2: 0.1W; SizeArea_mm2: 1.28; AEC Qualified: Y; VDC_V: 75V; AEC Category: Q200; AEC Grade: 0
R285 R296 R306 R323 = CMP-0022746-5: RES, 10.0 k, 1%, 0.1 W, 0603; Manufacturer: Yageo; Power_W: 100mW; TempCo: 100 ppm/C; Value_Code: 10k0; Value: 10.0k; EIA_Code: E96; Res_ohm: 10k; SizeX_mm: 1.6; SizeY_mm: 0.8; SizeZ_mm: 1; Value2: 0.1W; SizeArea_mm2: 1.28; AEC Qualified: N; VDC_V: 75V; AEC Category: Q200; SizeAreaWB_mm2: 4.68
R286 R297 R307 R324 = CMP-0022961-4: RES, 270 k, 1%, 0.1 W, 0603; Manufacturer: Yageo; Power_W: 100mW; TempCo: 100 ppm/C; Value: 270k; SizeX_mm: 1.6; SizeY_mm: 0.8; SizeZ_mm: 1; Value2: 0.1W; SizeArea_mm2: 1.28; AEC Qualified: N; VDC_V: 75V; AEC Category: Q200; SizeAreaWB_mm2: 4.68
R288 R299 R309 R326 = CMP-0022735-5: RES, 100 k, 1%, 0.1 W, 0603; Manufacturer: Yageo; Power_W: 100mW; TempCo: 100 ppm/C; Value: 100k; EIA_Code: E96; SizeX_mm: 1.6; SizeY_mm: 0.8; SizeZ_mm: 1; Value2: 0.1W; SizeArea_mm2: 1.28; AEC Qualified: N; VDC_V: 75V; AEC Category: Q200; SizeAreaWB_mm2: 4.68
R289 R300 R310 R327 = CMP-0023289-4: RES, 825 k, 1%, 0.1 W, 0603; Manufacturer: Yageo; Power_W: 100mW; TempCo: 100 ppm/C; Value: 825k; EIA_Code: E96; SizeX_mm: 1.6; SizeY_mm: 0.8; SizeZ_mm: 1; Value2: 0.1W; SizeArea_mm2: 1.28; AEC Qualified: N; VDC_V: 75V; AEC Category: Q200; SizeAreaWB_mm2: 4.68
R290 R301 R311 R328 = CMP-0023259-5: RES, 71.5 k, 1%, 0.1 W, 0603; Manufacturer: Yageo; Power_W: 100mW; TempCo: 100 ppm/C; Value_Code: 71k5; Value: 71.5k; EIA_Code: E96; SizeX_mm: 1.6; SizeY_mm: 0.8; SizeZ_mm: 1; Value2: 0.1W; SizeArea_mm2: 1.28; AEC Qualified: N; VDC_V: 75V; AEC Category: Q200; SizeAreaWB_mm2: 4.68
R293 = CMP-0026696-1: RES, 33.0, 1%, 0.1 W, 0402; Manufacturer: Panasonic; Power_W: 100mW; TempCo: 100 ppm/C; Value_Code: 33R0; U/M: EA; Value: 33.0; Res_ohm: 33; SizeX_mm: 1; SizeY_mm: 0.5; SizeZ_mm: 0.6; Value2: 0.1W; VDC_V: 50V; AEC Category: Q200
R312-R314 = CMP-0124370-1: 680 kOhms ±0.1% 0.2W, 1/5W Chip Resistor 0805 (2012 Metric) Anti-Sulfur, Automotive AEC-Q200, High Voltage, Moisture Resistant Thin Film; Manufacturer: Vishay; AEC Grade: Grade 1; AEC Qualified: Yes; Power_W: 200mW; SizeZ_mm: 0.55mm; TempCo: 25ppm/°C; VDC_V: 450V
R315 = CMP-0122747-1: 8 kOhms ±0.1% 0.1W, 1/10W Chip Resistor 0603 (1608 Metric) Thin Film; Manufacturer: Yageo; AEC Qualified: No; Power_W: 100mW; SizeZ_mm: 0.55mm; TempCo: 50ppm/°C; VDC_V: 75V
U27 U31 U36 U42 = CMP-0123798-1: Manufacturer: Texas Instruments; SizeZ_mm: 2.35mm; Standoff Height: 0mm
U28 U32 U37 U43 = CMP-0085676-1: High Speed, Robust EMC Reinforced Dual-Channel Digital Isolator, DWV0008A (SOIC-8); Alternate Manufacturer: Texas Instruments; Alternate PartNumber: ISO7721FDWVR; Rating: Catalog; SizeX_mm: 11.5; SizeArea_mm2: 67.275; CompType: IC; AEC Qualified: N; SizeY_mm: 5.85; SizeAreaWB_mm2: 105.975; SizeZ_mm: 2.8; AEC Category: Q200
U29 U34 U39 U44 = CMP-0120108-2: 1.5W, High-Density, >5 kVRMS Isolated DC-DC Converter; Manufacturer: Texas Instruments; SizeZ_mm: 2.6mm; AEC Qualified: No; Max Supply Voltage: 5.5V; Min Supply Voltage: 4.5V; Number Of Outputs: 1; Output Type: AdjustableProgrammable; Output Voltage: 5/5.5V; Standoff Height: 0.14mm; AEC Category: Q200; CompType: IC
U30 U35 U40 U45 = CMP-0013231-2: 28-V Output Voltage Boost Converter with Power Diode and Isolation Switch, DBV0006A (SOT-6); Manufacturer: Texas Instruments; Alternate PartNumber: TLV61046ADBVT; SizeX_mm: 2.8; SizeY_mm: 2.9; CompType: IC; SizeZ_mm: 1.45; SizeArea_mm2: 8.12; SizeAreaWB_mm2: 14.82; U/M: EA
U33 = CMP-0051217-4: Single 3-Input Positive-AND Gate, DRY0006A (USON-6); Manufacturer: Texas Instruments; Output Type: CMOS; Bits(#): 1; Input Type: CMOS/TTL; Technology Family: LVC; Schmitt Trigger: No; VCC(Max)(V): 5.5; Gate Type: AND; Rating: Catalog; Output Drive (IOL/IOH)(Max)(mA): 32/-32; ICC @ Nom Voltage(Max)(mA): 0.01; VCC(Min)(V): 1.65; F @ Nom Voltage(Max)(Mhz): 150; Logic: True; Voltage(Nom)(V): 1.8,2.5,3.3,5; tpd @ Nom Voltage(Max)(ns): 20,7.8,6.2,4.6; AEC Category: Q200; AEC Qualified: N; CompType: IC; SizeAreaWB_mm2: 4.9; SizeArea_mm2: 1.45; SizeX_mm: 1.0; SizeZ_mm: 0.6
U38 = CMP-0070963-2: Micropower, 150mA Low-Dropout CMOS Voltage Regulator, 5-pin SC-70, Pb-Free; Manufacturer: Texas Instruments; CompType: LDO IC; PackageTopMarking: L5B*XTT; PowerWise: N; AEC Category: Q200; SizeAreaWB_mm2: 9.3; SizeArea_mm2: 4.2; SizeX_mm: 2.1; SizeY_mm: 2.0; SizeZ_mm: 1.1
U41 = CMP-0124047-1: Precision, 2V Input, Basic and Reinforced Isolated Amplifiers With Fixed-Gain Differential Output; Manufacturer: Texas Instruments; SizeZ_mm: 2.8mm; AEC Qualified: No; Bandwidth: 110kHz; Input Bias Current: 3.5nA; Input Offset Voltage: 0.2mV; Max Supply Voltage: 5.5V; Min Supply Voltage: 3V; Number Of Channels: 1; Output Current Per Channel: 11mA; Response Time: 50us; Standoff Height: 0.36mm; TaMax_C: +125°C; TaMin_C: -40°C; TJmax_C: +150°C; Voltage Gain: 1V/V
